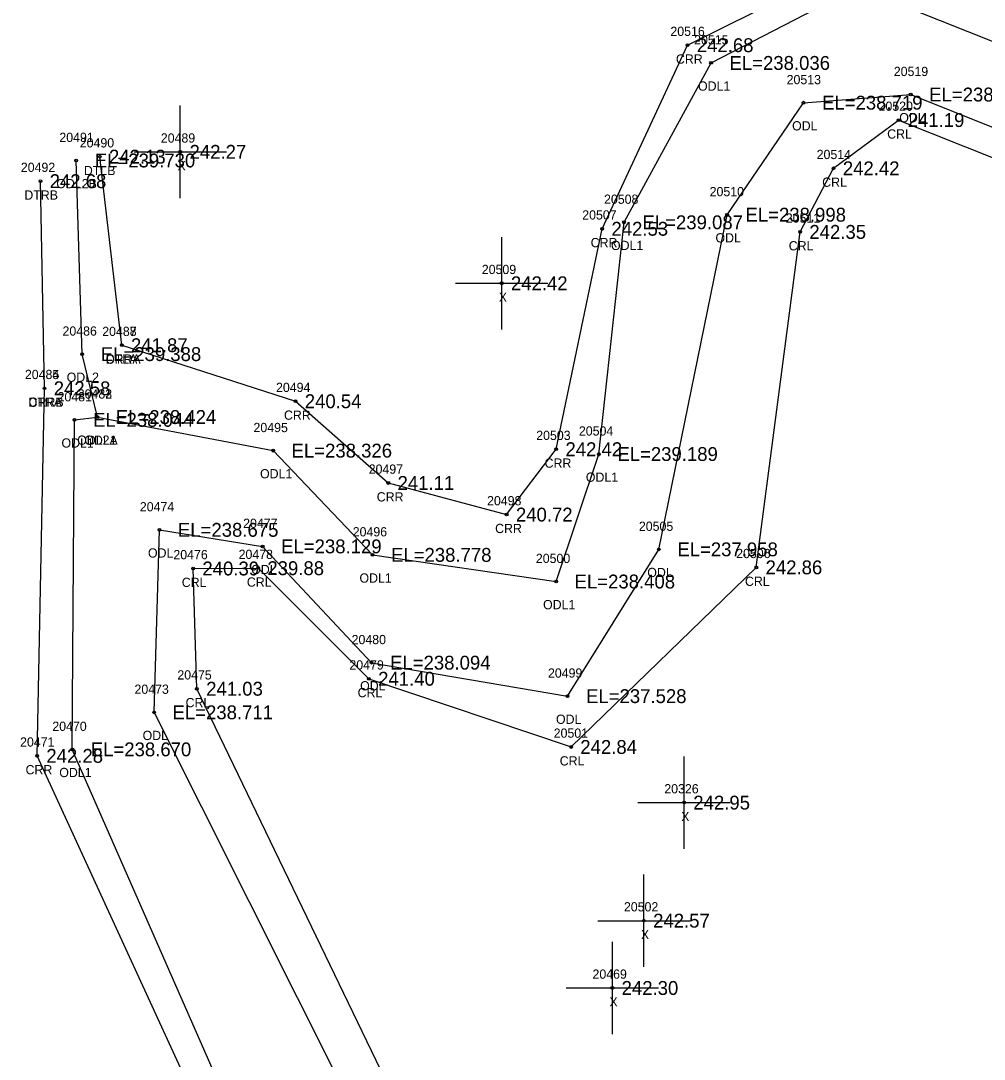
# Model space of a CAD drawing. Extents: x 2275563 to 2277161, y 1075719 to 1076412.
# Drawn here: x 2276295.7 to 2276399.9, y 1076142.9 to 1076255.2 of the extents above; entities that cross this region are included whole.
import ezdxf

# ---------------------------------------------------------------- set-up
doc = ezdxf.new("R2010")
doc.units = 0
for name, color, linetype in [('RD_EX_H2O', 7, 'Continuous'), ('RD_EX_H2O_txCode', 7, 'Continuous'), ('RD_EX_Misc', 7, 'Continuous'), ('RD_EX_Misc_txCode', 7, 'Continuous'), ('RD_EX_TX_H2O_ELEV', 7, 'Continuous'), ('RD_EX_TX_Misc_ELEV', 7, 'Continuous'), ('RD_SMD_Locator', 7, 'Continuous')]:
    doc.layers.add(name, color=color, linetype=linetype)

msp = doc.modelspace()

# ---------------------------------------------------------------- linework, layer by layer
at = {"layer": 'RD_EX_H2O'}
for p, q in [((2276306.58, 1076220.1), (2276304.2, 1076240.5)), ((2276298.22, 1076215.44), (2276297.78, 1076237.85))]:
    msp.add_line(p, q, dxfattribs=at)
for points in [[(2276374.66, 1076053.77), (2276377.62, 1076058.48), (2276375.93, 1076085.62), (2276365.46, 1076098.25), (2276358.16, 1076095.88), (2276352.82, 1076100.61), (2276340.06, 1076130.39), (2276314.72, 1076182.94), (2276314.31, 1076195.95), (2276321.34, 1076195.98), (2276333.33, 1076184.02), (2276355.21, 1076176.64), (2276375.26, 1076196.07), (2276380, 1076232.36), (2276383.62, 1076239.24), (2276390.64, 1076244.46), (2276451.84, 1076220.12), (2276472.79, 1076219.91), (2276480.77, 1076232.08), (2276477.11, 1076285.34), (2276453.42, 1076310.35), (2276458.35, 1076317.97), (2276489.24, 1076360.6), (2276498.15, 1076406.79)], [(2276337.52, 1076082.32), (2276338.14, 1076090.91), (2276325.39, 1076121.38), (2276301.23, 1076176.38), (2276301.47, 1076212.03), (2276303.94, 1076212.33), (2276322.96, 1076208.7), (2276333.72, 1076197.42), (2276353.59, 1076194.54), (2276358.22, 1076208.33), (2276360.94, 1076233.4), (2276370.36, 1076250.64), (2276386.18, 1076258.85), (2276454.86, 1076231.51), (2276469.16, 1076242), (2276461.94, 1076274.88), (2276441.6, 1076298.83), (2276443.32, 1076327.87), (2276470.76, 1076362.4), (2276481.62, 1076405.55)], [(2276371.99, 1076084.86), (2276359.12, 1076090.36), (2276349.87, 1076095.47), (2276335.93, 1076128.95), (2276310.08, 1076180.39), (2276310.66, 1076200.13), (2276321.83, 1076198.34), (2276333.62, 1076185.76), (2276354.83, 1076182.14), (2276364.71, 1076198.02), (2276372.09, 1076234.22), (2276380.37, 1076246.34), (2276391.97, 1076247.22), (2276452.13, 1076223.15), (2276471.36, 1076222.63), (2276478.94, 1076232.98), (2276472.33, 1076282.9), (2276448.49, 1076309.21), (2276451.67, 1076322.37), (2276482.4, 1076359.1), (2276495.19, 1076406.32)], [(2276306.58, 1076220.1), (2276325.39, 1076214.04), (2276335.43, 1076205.2), (2276348.24, 1076201.78), (2276353.6, 1076208.85), (2276358.58, 1076232.7), (2276367.82, 1076252.56), (2276386.4, 1076261.78), (2276453.31, 1076239.6), (2276463.95, 1076245.24), (2276459.26, 1076273.53), (2276439.87, 1076297.83), (2276438.91, 1076332.85), (2276467.89, 1076361.53), (2276478.69, 1076404.9)], [(2276303.94, 1076212.33), (2276302.31, 1076219.14), (2276301.66, 1076240.09)], [(2276334.2, 1076046.4), (2276323.43, 1076052.59), (2276325.46, 1076072.34), (2276328.54, 1076084.61), (2276333.7, 1076087.61), (2276328.57, 1076094.65), (2276321.53, 1076123.25), (2276297.42, 1076175.68), (2276298.22, 1076215.44)]]:
    msp.add_lwpolyline(points, dxfattribs=at)
at = {"layer": 'RD_EX_Misc'}
for p, q in [((2276312.92, 1076236.02), (2276312.92, 1076246.02)), ((2276307.92, 1076241.02), (2276317.92, 1076241.02)), ((2276347.7, 1076221.8), (2276347.7, 1076231.8)), ((2276342.7, 1076226.8), (2276352.7, 1076226.8)), ((2276367.44, 1076165.62), (2276367.44, 1076175.62)), ((2276362.44, 1076170.62), (2276372.44, 1076170.62)), ((2276363.09, 1076152.85), (2276363.09, 1076162.85)), ((2276358.09, 1076157.85), (2276368.09, 1076157.85)), ((2276359.68, 1076145.57), (2276359.68, 1076155.57)), ((2276354.68, 1076150.57), (2276364.68, 1076150.57))]:
    msp.add_line(p, q, dxfattribs=at)
at = {"layer": 'RD_SMD_Locator'}
for centre in [(2276367.82, 1076252.56), (2276370.36, 1076250.64), (2276391.97, 1076247.22), (2276380.37, 1076246.34), (2276390.64, 1076244.46), (2276301.66, 1076240.09), (2276304.2, 1076240.5), (2276312.92, 1076241.02), (2276383.62, 1076239.24), (2276297.78, 1076237.85), (2276360.94, 1076233.4), (2276372.09, 1076234.22), (2276358.58, 1076232.7), (2276380, 1076232.36), (2276347.7, 1076226.8), (2276306.58, 1076220.1), (2276306.58, 1076220.1), (2276302.31, 1076219.14), (2276298.22, 1076215.44), (2276298.22, 1076215.44), (2276325.39, 1076214.04), (2276301.47, 1076212.03), (2276303.94, 1076212.33), (2276303.94, 1076212.33), (2276322.96, 1076208.7), (2276353.6, 1076208.85), (2276358.22, 1076208.33), (2276335.43, 1076205.2), (2276348.24, 1076201.78), (2276310.66, 1076200.13), (2276321.83, 1076198.34), (2276333.72, 1076197.42), (2276364.71, 1076198.02), (2276314.31, 1076195.95), (2276321.34, 1076195.98), (2276375.26, 1076196.07), (2276353.59, 1076194.54), (2276333.62, 1076185.76), (2276333.33, 1076184.02), (2276314.72, 1076182.94), (2276354.83, 1076182.14), (2276310.08, 1076180.39), (2276301.23, 1076176.38), (2276355.21, 1076176.64), (2276297.42, 1076175.68), (2276367.44, 1076170.62), (2276363.09, 1076157.85), (2276359.68, 1076150.57)]:
    msp.add_circle(centre, 0.15, dxfattribs=at)

# ---------------------------------------------------------------- texts
at = {"layer": 'RD_EX_H2O_txCode'}
for s, p in [('20516', (2276365.96, 1076253.56)), ('20515', (2276368.53, 1076252.64)), ('CRR', (2276366.56, 1076250.56)), ('20519', (2276390.14, 1076249.22)), ('20513', (2276378.54, 1076248.34)), ('ODL1', (2276368.95, 1076247.64)), ('20520', (2276388.49, 1076245.46)), ('ODL', (2276390.73, 1076244.22)), ('ODL', (2276379.13, 1076243.34)), ('20491', (2276299.83, 1076242.09)), ('20490', (2276302.04, 1076241.5)), ('CRL', (2276389.42, 1076242.46)), ('20514', (2276381.79, 1076240.24)), ('20492', (2276295.66, 1076238.85)), ('DTLB', (2276302.48, 1076238.5)), ('ODL2B', (2276299.5, 1076237.09)), ('CRL', (2276382.39, 1076237.24)), ('DTRB', (2276296.04, 1076235.85)), ('20510', (2276370.21, 1076236.22)), ('20508', (2276358.78, 1076235.4)), ('20507', (2276356.42, 1076233.7)), ('20511', (2276378.45, 1076233.36)), ('CRR', (2276357.33, 1076230.7)), ('ODL1', (2276359.53, 1076230.4)), ('ODL', (2276370.84, 1076231.22)), ('CRL', (2276378.77, 1076230.36)), ('20486', (2276300.17, 1076221.14)), ('20487', (2276304.47, 1076221.1)), ('20488', (2276304.47, 1076221.1)), ('CRRA', (2276304.84, 1076218.1)), ('DTLA', (2276304.85, 1076218.1)), ('20484', (2276296.1, 1076216.44)), ('20485', (2276296.1, 1076216.44)), ('ODL2', (2276300.62, 1076216.14)), ('20494', (2276323.28, 1076215.04)), ('CRRB', (2276296.5, 1076213.44)), ('DTRA', (2276296.47, 1076213.44)), ('20481', (2276299.64, 1076214.03)), ('20482', (2276301.82, 1076214.33)), ('20483', (2276301.82, 1076214.33)), ('CRR', (2276324.14, 1076212.04)), ('20495', (2276320.84, 1076210.7)), ('20504', (2276356.06, 1076210.33)), ('ODL1', (2276300.06, 1076209.03)), ('ODL2A', (2276301.76, 1076209.33)), ('ODL1', (2276302.53, 1076209.33)), ('20503', (2276351.44, 1076209.85)), ('CRR', (2276352.35, 1076206.85)), ('ODL1', (2276321.55, 1076205.7)), ('20497', (2276333.31, 1076206.2)), ('ODL1', (2276356.81, 1076205.33)), ('CRR', (2276334.18, 1076203.2)), ('20474', (2276308.54, 1076202.13)), ('20498', (2276346.12, 1076202.78)), ('20477', (2276319.72, 1076200.34)), ('CRR', (2276346.99, 1076199.78)), ('20505', (2276362.55, 1076200.02)), ('20496', (2276331.58, 1076199.42)), ('ODL', (2276309.42, 1076197.13)), ('20476', (2276312.17, 1076196.95)), ('20478', (2276319.23, 1076196.98)), ('20500', (2276351.4, 1076196.54)), ('20506', (2276373.08, 1076197.07)), ('ODL', (2276320.59, 1076195.34)), ('ODL1', (2276332.31, 1076194.42)), ('ODL', (2276363.46, 1076195.02)), ('CRL', (2276313.08, 1076193.95)), ('CRL', (2276320.12, 1076193.98)), ('CRL', (2276374.03, 1076194.07)), ('ODL1', (2276352.18, 1076191.54)), ('20480', (2276331.46, 1076187.76)), ('20479', (2276331.22, 1076185.02)), ('20499', (2276352.71, 1076184.14)), ('20475', (2276312.6, 1076183.94)), ('20473', (2276307.96, 1076182.39)), ('CRL', (2276332.11, 1076182.02)), ('ODL', (2276332.38, 1076182.76)), ('CRL', (2276313.49, 1076180.94)), ('ODL', (2276353.58, 1076179.14)), ('20470', (2276299.07, 1076178.38)), ('ODL', (2276308.84, 1076177.39)), ('20501', (2276353.33, 1076177.64)), ('20471', (2276295.58, 1076176.68)), ('CRL', (2276353.98, 1076174.64)), ('CRR', (2276296.17, 1076173.68)), ('ODL1', (2276299.82, 1076173.38))]:
    msp.add_text(s, height=1, dxfattribs=at).set_placement(p)
at = {"layer": 'RD_EX_Misc_txCode'}
for s, p in [('20489', (2276310.81, 1076242.02)), ('X', (2276312.61, 1076239.02)), ('20509', (2276345.55, 1076227.8)), ('X', (2276347.39, 1076224.8)), ('20326', (2276365.3, 1076171.62)), ('X', (2276367.13, 1076168.62)), ('20502', (2276360.93, 1076158.85)), ('X', (2276362.77, 1076155.85)), ('20469', (2276357.53, 1076151.57)), ('X', (2276359.36, 1076148.57))]:
    msp.add_text(s, height=1, dxfattribs=at).set_placement(p)
at = {"layer": 'RD_EX_TX_H2O_ELEV'}
for s, p in [('242.68', (2276368.82, 1076251.81)), ('EL=238.036', (2276372.36, 1076249.89)), ('EL=238.293', (2276393.97, 1076246.47)), ('EL=238.719', (2276382.37, 1076245.59)), ('241.19', (2276391.64, 1076243.71)), ('242.13', (2276305.2, 1076239.75)), ('EL=239.730', (2276303.66, 1076239.34)), ('242.42', (2276384.62, 1076238.49)), ('242.68', (2276298.78, 1076237.1)), ('EL=238.998', (2276374.09, 1076233.47)), ('242.53', (2276359.58, 1076231.95)), ('EL=239.087', (2276362.94, 1076232.65)), ('242.35', (2276381, 1076231.61)), ('EL=239.388', (2276304.31, 1076218.39)), ('241.87', (2276307.58, 1076219.35)), ('241.87', (2276307.58, 1076219.35)), ('242.58', (2276299.22, 1076214.69)), ('242.58', (2276299.22, 1076214.69)), ('240.54', (2276326.39, 1076213.29)), ('EL=238.044', (2276303.47, 1076211.28)), ('EL=238.424', (2276305.94, 1076211.58)), ('EL=238.424', (2276305.94, 1076211.58)), ('EL=238.326', (2276324.96, 1076207.95)), ('242.42', (2276354.6, 1076208.1)), ('EL=239.189', (2276360.22, 1076207.58)), ('241.11', (2276336.43, 1076204.45)), ('240.72', (2276349.24, 1076201.03)), ('EL=238.675', (2276312.66, 1076199.38)), ('EL=238.129', (2276323.83, 1076197.59)), ('EL=237.958', (2276366.71, 1076197.27)), ('EL=238.778', (2276335.72, 1076196.67)), ('240.39', (2276315.31, 1076195.2)), ('239.88', (2276322.34, 1076195.23)), ('242.86', (2276376.26, 1076195.32)), ('EL=238.408', (2276355.59, 1076193.79)), ('EL=238.094', (2276335.62, 1076185.01)), ('241.40', (2276334.33, 1076183.27)), ('241.03', (2276315.72, 1076182.19)), ('EL=237.528', (2276356.83, 1076181.39)), ('EL=238.711', (2276312.08, 1076179.64)), ('242.84', (2276356.21, 1076175.89)), ('242.28', (2276298.42, 1076174.93)), ('EL=238.670', (2276303.23, 1076175.63))]:
    msp.add_text(s, height=1.5, dxfattribs=at).set_placement(p)
at = {"layer": 'RD_EX_TX_Misc_ELEV'}
for s, p in [('242.27', (2276313.92, 1076240.27)), ('242.42', (2276348.7, 1076226.05)), ('242.95', (2276368.44, 1076169.87)), ('242.57', (2276364.09, 1076157.1)), ('242.30', (2276360.68, 1076149.82))]:
    msp.add_text(s, height=1.5, dxfattribs=at).set_placement(p)

doc.saveas('drawing.dxf')
